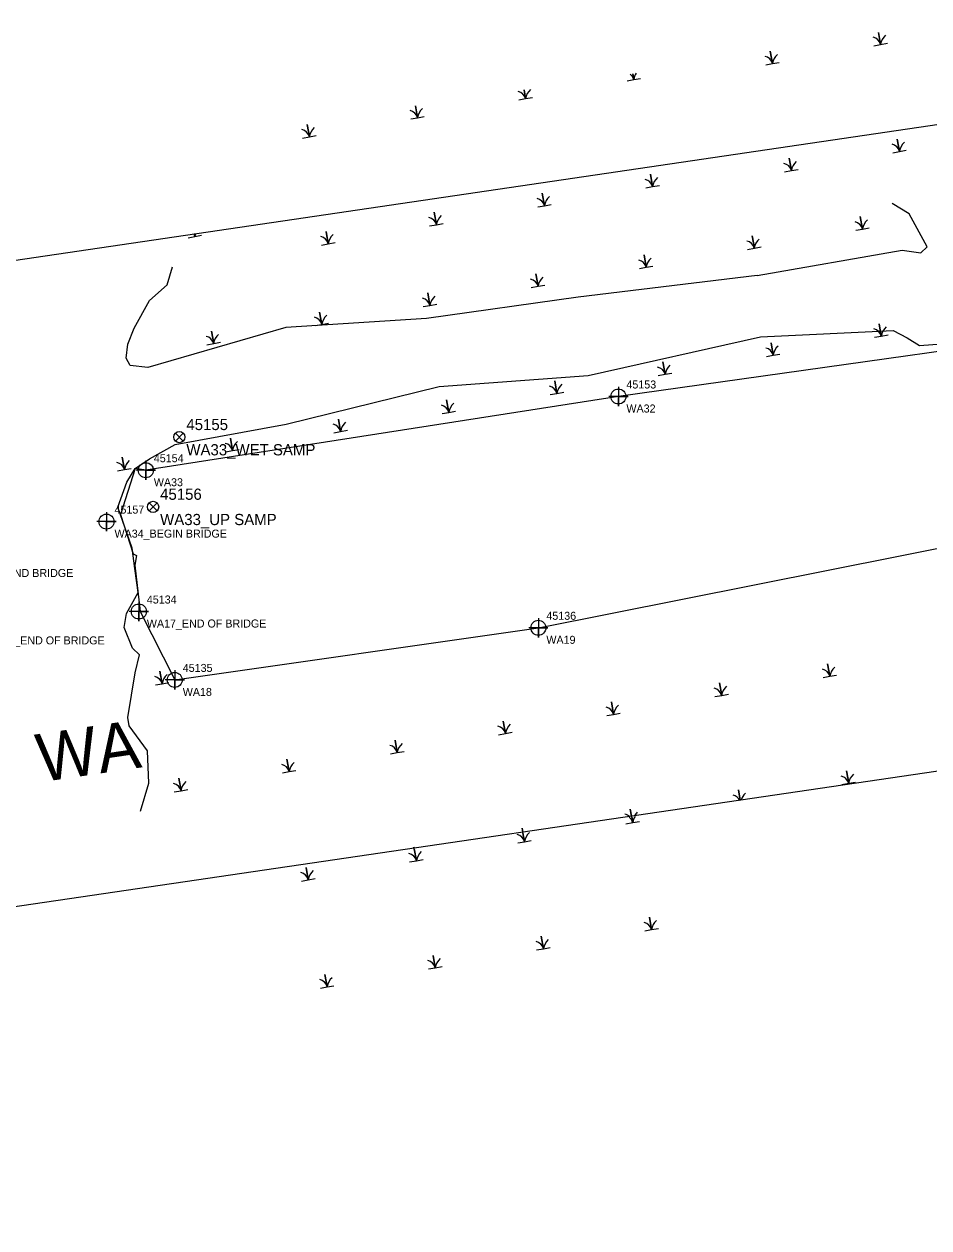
# Model space of a CAD drawing. Extents: x 2111078 to 2112839, y 581517 to 581907.
# Drawn here: x 2112071 to 2112353.6, y 581523.2 to 581899.2 of the extents above; entities that cross this region are included whole.
import ezdxf

# ---------------------------------------------------------------- set-up
doc = ezdxf.new("R2010")
doc.units = 0
for name, color, linetype in [('Default', 7, 'Continuous'), ('Exist Environmental Wetland Boundary', 7, 'Continuous'), ('Exist Environmental Wetland Boundary Cogo Comment', 7, 'Continuous'), ('Exist Environmental Wetland Boundary Cogo Number', 7, 'Continuous'), ('Exist Environmental Wetland Boundary Cogo Point CELL', 7, 'Continuous'), ('Exist Environmental Wetland Boundary Text', 7, 'Continuous'), ('Exist Hydro Jurisdictional Stream or Body of Water Mitigable', 7, 'Continuous'), ('Exist Hydro Swamp or Marsh', 7, 'Continuous')]:
    doc.layers.add(name, color=color, linetype=linetype)

msp = doc.modelspace()

# ---------------------------------------------------------------- linework, layer by layer
at = {"layer": 'Default'}
msp.add_lwpolyline([(2111089.87, 581523.16), (2111077.52, 581722.78), (2111579.66, 581753.48), (2112568.99, 581899.18), (2112598.13, 581701.32), (2111600.4, 581554.74), (2111516.52, 581549.55)], close=True, dxfattribs=at)
at = {"layer": 'Exist Environmental Wetland Boundary'}
msp.add_lwpolyline([(2112579.95, 581824.73), (2112443.39, 581809.13), (2112256.64, 581782.86), (2112109, 581759.83), (2112105.64, 581760.42), (2112101.13, 581745.95), (2112105.09, 581733.68), (2112106.09, 581733.21), (2112105.61, 581730.22), (2112107.23, 581715.72), (2112118.04, 581694.33), (2112231.63, 581710.61), (2112367.17, 581737.55), (2112425.86, 581731.24), (2112435.22, 581709.75), (2112484.9, 581686.89), (2112506.03, 581692.11), (2112548.3, 581765.77), (2112570.44, 581765.42), (2112537.9, 581733.37), (2112525.65, 581690.67)], dxfattribs=at)
at = {"layer": 'Exist Environmental Wetland Boundary Cogo Point CELL'}
for p, q in [((2112120.71, 581771.41), (2112118.24, 581768.93)), ((2112118.24, 581771.41), (2112120.71, 581768.93)), ((2112112.51, 581749.62), (2112110.03, 581747.15)), ((2112110.03, 581749.62), (2112112.51, 581747.15))]:
    msp.add_line(p, q, dxfattribs=at)
for points in [[(2112256.64, 581785.86), (2112256.64, 581779.86), (2112256.64, 581782.86), (2112259.64, 581782.86), (2112253.64, 581782.86)], [(2112109, 581762.83), (2112109, 581756.83), (2112109, 581759.83), (2112112, 581759.83), (2112106, 581759.83)], [(2112096.72, 581746.78), (2112096.72, 581740.78), (2112096.72, 581743.78), (2112099.72, 581743.78), (2112093.72, 581743.78)], [(2112106.82, 581718.7), (2112106.82, 581712.7), (2112106.82, 581715.7), (2112109.82, 581715.7), (2112103.82, 581715.7)], [(2112231.63, 581713.61), (2112231.63, 581707.61), (2112231.63, 581710.61), (2112234.63, 581710.61), (2112228.63, 581710.61)], [(2112118.04, 581697.33), (2112118.04, 581691.33), (2112118.04, 581694.33), (2112121.04, 581694.33), (2112115.04, 581694.33)]]:
    msp.add_lwpolyline(points, dxfattribs=at)
for centre, radius in [((2112256.64, 581782.86), 2.34), ((2112119.47, 581770.17), 1.75), ((2112109, 581759.83), 2.34), ((2112111.27, 581748.39), 1.75), ((2112096.72, 581743.78), 2.34), ((2112106.82, 581715.7), 2.34), ((2112231.63, 581710.61), 2.34), ((2112118.04, 581694.33), 2.34)]:
    msp.add_circle(centre, radius, dxfattribs=at)
at = {"layer": 'Exist Hydro Jurisdictional Stream or Body of Water Mitigable'}
for points in [[(2112100.23, 581748.26), (2112103.02, 581756.15), (2112105.64, 581760.42), (2112110.13, 581763.39), (2112118.12, 581767.86), (2112152.81, 581774.25), (2112200.61, 581786.03), (2112247.18, 581789.46), (2112301.01, 581801.47), (2112342.46, 581803.44), (2112346.85, 581801.19), (2112350.69, 581798.8), (2112399.61, 581802.48), (2112440.25, 581810.21), (2112440.58, 581811.7), (2112437.79, 581819.92), (2112440.2, 581821.93), (2112435.76, 581827.98), (2112435.27, 581831.28), (2112437.88, 581840.73), (2112494.44, 581874.08), (2112499.34, 581880.11)], [(2112299.97, 581820.62), (2112345.29, 581828.54), (2112351.14, 581827.75), (2112353.14, 581829.59), (2112347.44, 581839.95), (2112342.18, 581843.1)], [(2112299.97, 581820.62), (2112244.1, 581813.91), (2112196.72, 581807.25), (2112152.75, 581804.39), (2112109.6, 581791.96), (2112104.11, 581792.53), (2112102.88, 581794.8), (2112103.38, 581799.21), (2112105.36, 581804.23), (2112110.16, 581812.82), (2112115.62, 581817.75), (2112117.32, 581823.32)], [(2112102.93, 581715.03), (2112106.62, 581721.68), (2112105.59, 581729.17), (2112104.78, 581735.5), (2112100.23, 581748.26)], [(2112107.37, 581653.37), (2112109.93, 581662.07), (2112109.5, 581672.16), (2112103.77, 581679.97), (2112103.37, 581682.62), (2112105.67, 581696.57), (2112106.99, 581702.2), (2112104.89, 581704.27), (2112102.25, 581710.71), (2112102.93, 581715.03)]]:
    msp.add_lwpolyline(points, dxfattribs=at)
at = {"layer": 'Exist Hydro Swamp or Marsh'}
for points in [[(2112336.43, 581892.43), (2112338.55, 581892.81), (2112337.9, 581896.52)], [(2112337.9, 581896.52), (2112338.55, 581892.81), (2112340.67, 581893.18)], [(2112302.65, 581886.48), (2112304.77, 581886.85), (2112304.09, 581890.74), (2112304.77, 581886.85), (2112306.89, 581887.22)], [(2112259.32, 581881.47), (2112261.43, 581881.85), (2112261.12, 581883.64)], [(2112261.12, 581883.64), (2112261.43, 581881.85), (2112263.55, 581882.22)], [(2112225.54, 581875.52), (2112227.65, 581875.89), (2112227.17, 581878.64)], [(2112227.17, 581878.64), (2112227.65, 581875.89), (2112229.77, 581876.26)], [(2112191.76, 581869.56), (2112193.87, 581869.93), (2112193.22, 581873.64)], [(2112193.22, 581873.64), (2112193.87, 581869.93), (2112195.99, 581870.31)], [(2112157.98, 581863.6), (2112160.09, 581863.98), (2112159.41, 581867.86), (2112160.09, 581863.98), (2112162.21, 581864.35)], [(2112342.33, 581859), (2112344.45, 581859.38), (2112343.76, 581863.26), (2112344.45, 581859.38), (2112346.56, 581859.75)], [(2112308.55, 581853.05), (2112310.67, 581853.42), (2112309.98, 581857.31), (2112310.67, 581853.42), (2112312.78, 581853.8)], [(2112265.21, 581848.04), (2112267.33, 581848.42), (2112266.64, 581852.3), (2112267.33, 581848.42), (2112269.45, 581848.79)], [(2112231.43, 581842.09), (2112233.55, 581842.46), (2112232.86, 581846.35), (2112233.55, 581842.46), (2112235.67, 581842.83)], [(2112197.65, 581836.13), (2112199.77, 581836.5), (2112199.08, 581840.39), (2112199.77, 581836.5), (2112201.89, 581836.88)], [(2112330.76, 581834.77), (2112332.88, 581835.14), (2112332.19, 581839.03), (2112332.88, 581835.14), (2112334.99, 581835.51)], [(2112122.19, 581832.46), (2112124.3, 581832.83), (2112124.16, 581833.67)], [(2112124.16, 581833.67), (2112124.3, 581832.83), (2112126.42, 581833.21)], [(2112163.87, 581830.17), (2112165.99, 581830.55), (2112165.3, 581834.43), (2112165.99, 581830.55), (2112168.11, 581830.92)], [(2112296.98, 581828.81), (2112299.1, 581829.18), (2112298.41, 581833.07), (2112299.1, 581829.18), (2112301.21, 581829.56)], [(2112263.2, 581822.85), (2112265.32, 581823.23), (2112264.63, 581827.11), (2112265.32, 581823.23), (2112267.44, 581823.6)], [(2112229.42, 581816.9), (2112231.54, 581817.27), (2112230.85, 581821.16), (2112231.54, 581817.27), (2112233.66, 581817.64)], [(2112195.64, 581810.94), (2112197.76, 581811.31), (2112197.07, 581815.2), (2112197.76, 581811.31), (2112199.88, 581811.69)], [(2112161.86, 581804.99), (2112163.98, 581805.36), (2112163.29, 581809.24), (2112163.98, 581805.36), (2112166.1, 581805.73)], [(2112336.65, 581801.34), (2112338.77, 581801.71), (2112338.09, 581805.6), (2112338.77, 581801.71), (2112340.89, 581802.08)], [(2112128.08, 581799.03), (2112130.2, 581799.4), (2112129.51, 581803.29), (2112130.2, 581799.4), (2112132.32, 581799.78)], [(2112302.87, 581795.38), (2112304.99, 581795.75), (2112304.31, 581799.64), (2112304.99, 581795.75), (2112307.11, 581796.13)], [(2112269.09, 581789.42), (2112271.21, 581789.8), (2112270.53, 581793.68), (2112271.21, 581789.8), (2112273.33, 581790.17)], [(2112235.31, 581783.47), (2112237.43, 581783.84), (2112236.75, 581787.73), (2112237.43, 581783.84), (2112239.55, 581784.21)], [(2112201.53, 581777.51), (2112203.65, 581777.89), (2112202.97, 581781.77), (2112203.65, 581777.89), (2112205.77, 581778.26)], [(2112167.76, 581771.56), (2112169.87, 581771.93), (2112169.19, 581775.81), (2112169.87, 581771.93), (2112171.99, 581772.3)], [(2112133.98, 581765.6), (2112136.09, 581765.97), (2112135.41, 581769.86), (2112136.09, 581765.97), (2112138.21, 581766.35)], [(2112100.2, 581759.64), (2112102.31, 581760.02), (2112101.63, 581763.9), (2112102.31, 581760.02), (2112104.43, 581760.39)], [(2112320.56, 581695.09), (2112322.68, 581695.47), (2112321.99, 581699.35), (2112322.68, 581695.47), (2112324.79, 581695.84)], [(2112111.98, 581692.78), (2112114.1, 581693.16), (2112113.42, 581697.04), (2112114.1, 581693.16), (2112116.22, 581693.53)], [(2112286.78, 581689.14), (2112288.9, 581689.51), (2112288.21, 581693.39), (2112288.9, 581689.51), (2112291.01, 581689.88)], [(2112253, 581683.18), (2112255.12, 581683.55), (2112254.43, 581687.44), (2112255.12, 581683.55), (2112257.23, 581683.93)], [(2112219.22, 581677.22), (2112221.34, 581677.6), (2112220.65, 581681.48), (2112221.34, 581677.6), (2112223.45, 581677.97)], [(2112185.44, 581671.27), (2112187.56, 581671.64), (2112186.87, 581675.53), (2112187.56, 581671.64), (2112189.67, 581672.01)], [(2112151.66, 581665.31), (2112153.78, 581665.68), (2112153.09, 581669.57), (2112153.78, 581665.68), (2112155.89, 581666.06)], [(2112326.45, 581661.66), (2112328.57, 581662.04), (2112327.88, 581665.92), (2112328.57, 581662.04), (2112330.69, 581662.41)], [(2112117.88, 581659.35), (2112120, 581659.73), (2112119.31, 581663.61), (2112120, 581659.73), (2112122.11, 581660.1)], [(2112294.67, 581656.74), (2112294.1, 581659.97), (2112294.67, 581656.74)], [(2112258.98, 581649.38), (2112261.1, 581649.75), (2112260.78, 581651.55)], [(2112260.72, 581651.75), (2112260.33, 581654.01), (2112260.72, 581651.75)], [(2112260.78, 581651.55), (2112261.1, 581649.75), (2112263.21, 581650.13)], [(2112226.77, 581646.76), (2112226.55, 581648.05), (2112226.77, 581646.76)], [(2112225.2, 581643.42), (2112227.32, 581643.8), (2112226.83, 581646.55)], [(2112226.83, 581646.55), (2112227.32, 581643.8), (2112229.43, 581644.17)], [(2112191.42, 581637.47), (2112193.54, 581637.84), (2112192.88, 581641.55)], [(2112192.82, 581641.77), (2112192.77, 581642.1), (2112192.82, 581641.77)], [(2112192.88, 581641.55), (2112193.54, 581637.84), (2112195.65, 581638.22)], [(2112157.64, 581631.51), (2112159.76, 581631.89), (2112159.07, 581635.77), (2112159.76, 581631.89), (2112161.87, 581632.26)], [(2112264.87, 581615.95), (2112266.99, 581616.33), (2112266.3, 581620.21), (2112266.99, 581616.33), (2112269.11, 581616.7)], [(2112231.09, 581610), (2112233.21, 581610.37), (2112232.53, 581614.25), (2112233.21, 581610.37), (2112235.33, 581610.74)], [(2112197.31, 581604.04), (2112199.43, 581604.41), (2112198.75, 581608.3), (2112199.43, 581604.41), (2112201.55, 581604.79)], [(2112163.53, 581598.08), (2112165.65, 581598.46), (2112164.97, 581602.34), (2112165.65, 581598.46), (2112167.77, 581598.83)]]:
    msp.add_lwpolyline(points, dxfattribs=at)
for centre, radius, start, end in [((2112335.57, 581892.06), 3.07, 14.1403, 77.535), ((2112343.31, 581892.11), 4.81, 132.1274, 171.6222), ((2112301.79, 581886.1), 3.07, 14.1403, 77.535), ((2112309.53, 581886.15), 4.81, 132.1274, 171.6222), ((2112266.19, 581881.15), 4.81, 146.4858, 171.6222), ((2112258.45, 581881.09), 3.07, 14.1403, 52.2834), ((2112224.67, 581875.14), 3.07, 14.1403, 77.535), ((2112232.41, 581875.19), 4.81, 132.1274, 171.6222), ((2112198.63, 581869.23), 4.81, 132.1274, 171.6222), ((2112190.89, 581869.18), 3.07, 14.1403, 77.535), ((2112157.11, 581863.23), 3.07, 14.1403, 77.535), ((2112164.85, 581863.28), 4.81, 132.1274, 171.6222), ((2112341.46, 581858.63), 3.07, 14.1403, 77.535), ((2112349.2, 581858.68), 4.81, 132.1274, 171.6222), ((2112307.69, 581852.67), 3.07, 14.1403, 77.535), ((2112315.42, 581852.72), 4.81, 132.1274, 171.6222), ((2112264.35, 581847.67), 3.07, 14.1403, 77.535), ((2112272.08, 581847.72), 4.81, 132.1274, 171.6222), ((2112230.57, 581841.71), 3.07, 14.1403, 77.535), ((2112238.3, 581841.76), 4.81, 132.1274, 171.6222), ((2112196.79, 581835.75), 3.07, 14.1403, 77.535), ((2112204.52, 581835.8), 4.81, 132.1274, 171.6222), ((2112329.9, 581834.39), 3.07, 14.1403, 77.535), ((2112337.63, 581834.44), 4.81, 132.1274, 171.6222), ((2112121.32, 581832.08), 3.07, 14.1403, 30.5701), ((2112129.06, 581832.13), 4.81, 160.6216, 171.6222), ((2112163.01, 581829.8), 3.07, 14.1403, 77.535), ((2112170.74, 581829.85), 4.81, 132.1274, 171.6222), ((2112296.12, 581828.43), 3.07, 14.1403, 77.535), ((2112303.85, 581828.48), 4.81, 132.1274, 171.6222), ((2112262.34, 581822.48), 3.07, 14.1403, 77.535), ((2112270.07, 581822.53), 4.81, 132.1274, 171.6222), ((2112236.29, 581816.57), 4.81, 132.1274, 171.6222), ((2112228.56, 581816.52), 3.07, 14.1403, 77.535), ((2112194.78, 581810.56), 3.07, 14.1403, 77.535), ((2112202.51, 581810.61), 4.81, 132.1274, 171.6222), ((2112161, 581804.61), 3.07, 14.1403, 77.535), ((2112168.73, 581804.66), 4.81, 132.1274, 171.6222), ((2112343.53, 581801.01), 4.81, 132.1274, 171.6222), ((2112127.22, 581798.65), 3.07, 14.1403, 77.535), ((2112134.95, 581798.7), 4.81, 132.1274, 171.6222), ((2112335.79, 581800.96), 3.07, 14.1403, 77.535), ((2112302.01, 581795), 3.07, 14.1403, 77.535), ((2112309.75, 581795.05), 4.81, 132.1274, 171.6222), ((2112268.23, 581789.05), 3.07, 14.1403, 77.535), ((2112275.97, 581789.1), 4.81, 132.1274, 171.6222), ((2112234.45, 581783.09), 3.07, 14.1403, 77.535), ((2112242.19, 581783.14), 4.81, 132.1274, 171.6222), ((2112200.67, 581777.13), 3.07, 14.1403, 77.535), ((2112208.41, 581777.19), 4.81, 132.1274, 171.6222), ((2112174.63, 581771.23), 4.81, 132.1274, 171.6222), ((2112166.89, 581771.18), 3.07, 14.1403, 77.535), ((2112133.11, 581765.22), 3.07, 14.1403, 77.535), ((2112140.85, 581765.27), 4.81, 132.1274, 171.6222), ((2112099.33, 581759.27), 3.07, 14.1403, 77.535), ((2112107.07, 581759.32), 4.81, 132.1274, 171.6222), ((2112118.86, 581692.46), 4.81, 132.1274, 171.6222), ((2112319.69, 581694.71), 3.07, 14.1403, 77.535), ((2112327.43, 581694.77), 4.81, 132.1274, 171.6222), ((2112111.12, 581692.41), 3.07, 14.1403, 77.535), ((2112293.65, 581688.81), 4.81, 132.1274, 171.6222), ((2112285.91, 581688.76), 3.07, 14.1403, 77.535), ((2112252.13, 581682.8), 3.07, 14.1403, 77.535), ((2112259.87, 581682.85), 4.81, 132.1274, 171.6222), ((2112218.35, 581676.85), 3.07, 14.1403, 77.535), ((2112226.09, 581676.9), 4.81, 132.1274, 171.6222), ((2112184.57, 581670.89), 3.07, 14.1403, 77.535), ((2112192.31, 581670.94), 4.81, 132.1274, 171.6222), ((2112150.8, 581664.93), 3.07, 14.1403, 77.535), ((2112158.53, 581664.98), 4.81, 132.1274, 171.6222), ((2112117.02, 581658.98), 3.07, 14.1403, 77.535), ((2112124.75, 581659.03), 4.81, 132.1274, 171.6222), ((2112325.59, 581661.29), 3.07, 14.1403, 77.535), ((2112333.32, 581661.34), 4.81, 132.1274, 171.6222), ((2112291.81, 581655.33), 3.07, 26.8826, 77.535), ((2112299.54, 581655.38), 4.81, 132.1274, 163.0953), ((2112258.03, 581649.37), 3.07, 47.9571, 77.535), ((2112258.11, 581649), 3.07, 14.1403, 52.2834), ((2112265.85, 581649.05), 4.81, 146.4858, 171.6222), ((2112265.76, 581649.42), 4.81, 132.1274, 149.2113), ((2112232.07, 581643.1), 4.81, 132.1274, 171.6222), ((2112224.33, 581643.05), 3.07, 14.1403, 77.535), ((2112190.55, 581637.09), 3.07, 14.1403, 77.535), ((2112198.29, 581637.14), 4.81, 132.1274, 171.6222), ((2112156.77, 581631.13), 3.07, 14.1403, 77.535), ((2112164.51, 581631.19), 4.81, 132.1274, 171.6222), ((2112264.01, 581615.57), 3.07, 14.1403, 77.535), ((2112271.74, 581615.62), 4.81, 132.1274, 171.6222), ((2112237.96, 581609.67), 4.81, 132.1274, 171.6222), ((2112230.23, 581609.62), 3.07, 14.1403, 77.535), ((2112196.45, 581603.66), 3.07, 14.1403, 77.535), ((2112204.18, 581603.71), 4.81, 132.1274, 171.6222), ((2112162.67, 581597.71), 3.07, 14.1403, 77.535), ((2112170.41, 581597.76), 4.81, 132.1274, 171.6222)]:
    msp.add_arc(centre, radius, start, end, dxfattribs=at)

# ---------------------------------------------------------------- texts
at = {"layer": 'Exist Environmental Wetland Boundary Cogo Comment'}
for s, p in [('WA32', (2112259.14, 581777.86)), ('WA33', (2112111.5, 581754.83)), ('WA34_BEGIN BRIDGE', (2112099.22, 581738.78)), ('WA35_END BRIDGE', (2112054.58, 581726.48)), ('WA17_END OF BRIDGE', (2112109.32, 581710.7)), ('WA16_END OF BRIDGE', (2112058.8, 581705.43)), ('WA19', (2112234.13, 581705.61)), ('WA18', (2112120.54, 581689.33))]:
    msp.add_text(s, height=2.5, dxfattribs=at).set_placement(p)
at = {"layer": 'Exist Environmental Wetland Boundary Cogo Number'}
for s, p in [('45153', (2112259.14, 581785.36)), ('45154', (2112111.5, 581762.33)), ('45157', (2112099.22, 581746.28)), ('45134', (2112109.32, 581718.2)), ('45136', (2112234.13, 581713.11)), ('45135', (2112120.54, 581696.83))]:
    msp.add_text(s, height=2.5, dxfattribs=at).set_placement(p)
at = {"layer": 'Exist Environmental Wetland Boundary Text'}
for s, p in [('45155', (2112121.67, 581772.37)), ('WA33_WET SAMP', (2112121.67, 581764.47)), ('45156', (2112113.47, 581750.59)), ('WA33_UP SAMP', (2112113.47, 581742.69))]:
    msp.add_text(s, height=3.5, dxfattribs=at).set_placement(p)
msp.add_text('WA', height=15, rotation=8.3579, dxfattribs=at).set_placement((2112076.08, 581662.36))

doc.saveas('drawing.dxf')
